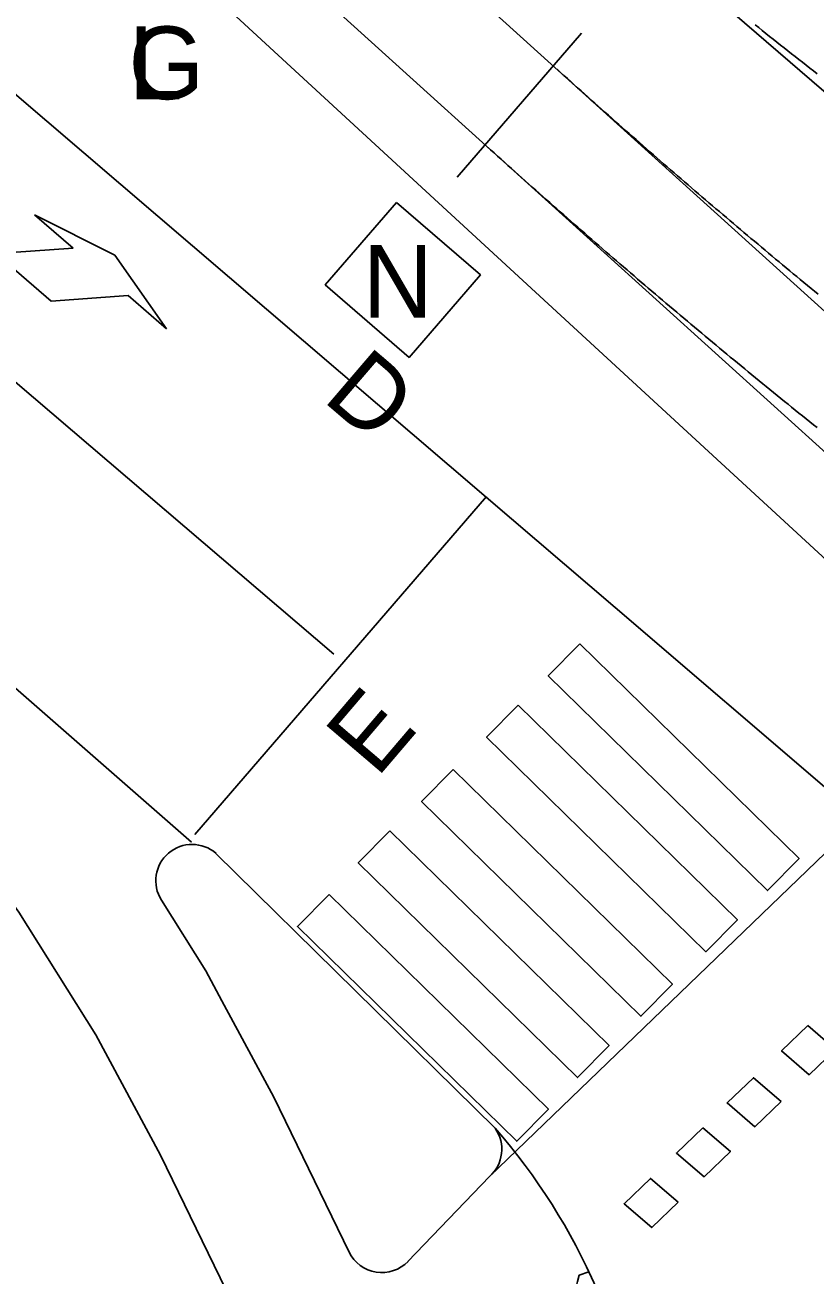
# Model space of a CAD drawing. Extents: x 81617 to 82144, y 454649 to 455150.
# Drawn here: x 81667.23 to 81678.09, y 454739.6 to 454756.79 of the extents above; entities that cross this region are included whole.
import ezdxf

# ---------------------------------------------------------------- set-up
doc = ezdxf.new("R2010")
doc.units = 0
doc.layers.add('B-WE-OG-TOPOGRAFIE-G', color=7, linetype='Continuous')
doc.layers.add('B-WE-VW-MARKERING-G', color=7, linetype='Continuous')

msp = doc.modelspace()

# ---------------------------------------------------------------- linework, layer by layer
at = {"layer": 'B-WE-OG-TOPOGRAFIE-G'}
for p, q in [((81665.037, 454761.611), (81680.379, 454747.473)), ((81675.346, 454748.781), (81678.385, 454746.18)), ((81673.616, 454740.954), (81679.057, 454746.2)), ((81669.855, 454745.401), (81673.694, 454741.62)), ((81672.496, 454739.789), (81673.616, 454740.954)), ((81674.852, 454739.601), (81674.985, 454739.646))]:
    msp.add_line(p, q, dxfattribs=at)
for points in [[(81679.74, 454754.574), (81638.311, 454790.255)], [(81648.409, 454771.836), (81673.57, 454750.3)], [(81667.129, 454762.89), (81692.29, 454740.147), (81692.29, 454740.147), (81692.424, 454740.026), (81692.557, 454739.905), (81692.691, 454739.784), (81692.825, 454739.663), (81692.959, 454739.542)], [(81666.167, 454761.826), (81691.328, 454739.082)], [(81678.126, 454756.124), (81678.075, 454756.163), (81678.025, 454756.202), (81677.974, 454756.242), (81677.924, 454756.281), (81677.873, 454756.321), (81677.823, 454756.361), (81677.773, 454756.4), (81677.722, 454756.44), (81677.672, 454756.479), (81677.621, 454756.519), (81677.571, 454756.559), (81677.521, 454756.599), (81677.471, 454756.638), (81677.42, 454756.678), (81677.37, 454756.718), (81677.32, 454756.758), (81677.27, 454756.798)], [(81674.548, 454756.185), (81674.595, 454756.142), (81674.641, 454756.1), (81674.688, 454756.058), (81674.735, 454756.015), (81674.782, 454755.973), (81674.829, 454755.931), (81674.876, 454755.889), (81674.924, 454755.847), (81674.971, 454755.805), (81675.018, 454755.762), (81675.065, 454755.72), (81675.112, 454755.678), (81675.159, 454755.636), (81675.206, 454755.594), (81675.254, 454755.552), (81675.301, 454755.511), (81675.348, 454755.469), (81675.396, 454755.427), (81675.443, 454755.385), (81675.49, 454755.343), (81675.538, 454755.301), (81675.585, 454755.26), (81675.633, 454755.218), (81675.68, 454755.176), (81675.728, 454755.135), (81675.775, 454755.093), (81675.823, 454755.052), (81675.871, 454755.01), (81675.918, 454754.969), (81675.966, 454754.927), (81676.013, 454754.886), (81676.061, 454754.844), (81676.109, 454754.803), (81676.157, 454754.761), (81676.204, 454754.72), (81676.252, 454754.679), (81676.3, 454754.638), (81676.348, 454754.596), (81676.396, 454754.555), (81676.444, 454754.514), (81676.492, 454754.473), (81676.54, 454754.432), (81676.588, 454754.391), (81676.636, 454754.35), (81676.684, 454754.309), (81676.732, 454754.268), (81676.78, 454754.227), (81676.828, 454754.186), (81676.876, 454754.145), (81676.924, 454754.104), (81676.973, 454754.063), (81677.021, 454754.022), (81677.069, 454753.981), (81677.117, 454753.941), (81677.166, 454753.9), (81677.214, 454753.859), (81677.262, 454753.819), (81677.311, 454753.778), (81677.359, 454753.737), (81677.408, 454753.697), (81677.456, 454753.656), (81677.505, 454753.616), (81677.553, 454753.575), (81677.602, 454753.535), (81677.65, 454753.495), (81677.699, 454753.454), (81677.747, 454753.414), (81677.796, 454753.374), (81677.845, 454753.333), (81677.893, 454753.293), (81677.942, 454753.253), (81677.991, 454753.213), (81678.04, 454753.172), (81678.088, 454753.132), (81678.137, 454753.092)], [(81673.585, 454755.12), (81673.633, 454755.077), (81673.681, 454755.034), (81673.728, 454754.991), (81673.776, 454754.948), (81673.823, 454754.906), (81673.871, 454754.863), (81673.919, 454754.82), (81673.967, 454754.777), (81674.014, 454754.734), (81674.062, 454754.692), (81674.11, 454754.649), (81674.158, 454754.606), (81674.206, 454754.564), (81674.254, 454754.521), (81674.302, 454754.479), (81674.35, 454754.436), (81674.398, 454754.394), (81674.446, 454754.351), (81674.494, 454754.309), (81674.542, 454754.267), (81674.59, 454754.224), (81674.638, 454754.182), (81674.686, 454754.14), (81674.734, 454754.097), (81674.783, 454754.055), (81674.831, 454754.013), (81674.879, 454753.971), (81674.927, 454753.929), (81674.976, 454753.886), (81675.024, 454753.844), (81675.072, 454753.802), (81675.121, 454753.76), (81675.169, 454753.718), (81675.218, 454753.676), (81675.266, 454753.634), (81675.315, 454753.593), (81675.363, 454753.551), (81675.412, 454753.509), (81675.46, 454753.467), (81675.509, 454753.425), (81675.558, 454753.384), (81675.606, 454753.342), (81675.655, 454753.3), (81675.704, 454753.259), (81675.752, 454753.217), (81675.801, 454753.175), (81675.85, 454753.134), (81675.899, 454753.092), (81675.948, 454753.051), (81675.997, 454753.009), (81676.045, 454752.968), (81676.094, 454752.926), (81676.143, 454752.885), (81676.192, 454752.844), (81676.241, 454752.802), (81676.29, 454752.761), (81676.339, 454752.72), (81676.388, 454752.679), (81676.438, 454752.638), (81676.487, 454752.596), (81676.536, 454752.555), (81676.585, 454752.514), (81676.634, 454752.473), (81676.684, 454752.432), (81676.733, 454752.391), (81676.782, 454752.35), (81676.831, 454752.309), (81676.881, 454752.268), (81676.93, 454752.227), (81676.98, 454752.187), (81677.029, 454752.146), (81677.078, 454752.105), (81677.128, 454752.064), (81677.177, 454752.024), (81677.227, 454751.983), (81677.276, 454751.942), (81677.326, 454751.902), (81677.376, 454751.861), (81677.425, 454751.821), (81677.475, 454751.78), (81677.525, 454751.74), (81677.574, 454751.699), (81677.624, 454751.659), (81677.674, 454751.618), (81677.724, 454751.578), (81677.773, 454751.538), (81677.823, 454751.497), (81677.873, 454751.457), (81677.923, 454751.417), (81677.973, 454751.377), (81678.023, 454751.336), (81678.073, 454751.296), (81678.123, 454751.256)], [(81672.339, 454754.355), (81673.493, 454753.357), (81672.511, 454752.222), (81671.358, 454753.221), (81672.339, 454754.355)], [(81673.57, 454750.3), (81675.346, 454748.781)], [(81670.568, 454738.214), (81669.091, 454741.249), (81668.201, 454742.903), (81667.143, 454744.591), (81666.308, 454745.728), (81665.415, 454746.82), (81664.464, 454747.862)], [(81669.937, 454743.37), (81669.715, 454743.783), (81669.104, 454744.758)], [(81671.686, 454739.917), (81670.649, 454742.047), (81669.937, 454743.37)]]:
    msp.add_lwpolyline(points, dxfattribs=at)
for centre, radius, start, end in [((81669.527, 454745.023), 0.5, 48.9814, 212.0769), ((81673.286, 454741.33), 0.5, 311.2239, 35.4425), ((81667.367, 454736.072), 8.414, 5.6174, 41.2493), ((81672.136, 454740.135), 0.5, 205.9555, 316.1334), ((81677.483, 454738.825), 2.743, 163.57, 224.2627)]:
    msp.add_arc(centre, radius, start, end, dxfattribs=at)
at = {"layer": 'B-WE-VW-MARKERING-G'}
for p, q in [((81649.533, 454763.036), (81669.519, 454745.553)), ((81674.885, 454756.684), (81673.173, 454754.7)), ((81664.899, 454755.313), (81667.588, 454752.995)), ((81671.474, 454748.14), (81664.21, 454754.35)), ((81668.463, 454753.627), (81667.358, 454754.183)), ((81667.358, 454754.183), (81667.888, 454753.726)), ((81667.888, 454753.726), (81667.042, 454753.664)), ((81669.176, 454752.616), (81668.463, 454753.627)), ((81667.588, 454752.995), (81668.646, 454753.073)), ((81668.646, 454753.073), (81669.176, 454752.616)), ((81673.576, 454750.308), (81669.565, 454745.66))]:
    msp.add_line(p, q, dxfattribs=at)
for points in [[(81674.86, 454748.281), (81677.876, 454745.328), (81677.442, 454744.888), (81674.426, 454747.841)], [(81674.011, 454747.44), (81677.028, 454744.487), (81676.594, 454744.047), (81673.577, 454747)], [(81673.117, 454746.553), (81676.133, 454743.601), (81675.699, 454743.161), (81672.683, 454746.114)], [(81672.246, 454745.71), (81675.263, 454742.757), (81674.829, 454742.317), (81671.812, 454745.27)], [(81671.41, 454744.833), (81674.427, 454741.88), (81673.993, 454741.44), (81670.976, 454744.393)], [(81677.997, 454743.031), (81678.378, 454742.704), (81678.016, 454742.356), (81677.635, 454742.683)], [(81677.63, 454741.988), (81677.248, 454742.315), (81676.886, 454741.967), (81677.268, 454741.64)], [(81676.551, 454741.627), (81676.932, 454741.3), (81676.571, 454740.952), (81676.189, 454741.278)], [(81676.212, 454740.603), (81675.83, 454740.929), (81675.468, 454740.581), (81675.85, 454740.254)]]:
    msp.add_lwpolyline(points, close=True, dxfattribs=at)

# ---------------------------------------------------------------- texts
at = {"layer": 'B-WE-OG-TOPOGRAFIE-G'}
for s, p in [('G', (81668.652, 454755.774)), ('L', (81668.652, 454755.774)), ('N', (81671.874, 454752.768))]:
    msp.add_text(s, height=1, dxfattribs=at).set_placement(p)
for s, rotation, p in [('D', 319.4397, (81671.302, 454751.639)), ('E', 49.5421, (81672.066, 454746.423))]:
    msp.add_text(s, height=1, rotation=rotation, dxfattribs=at).set_placement(p)

doc.saveas('drawing.dxf')
